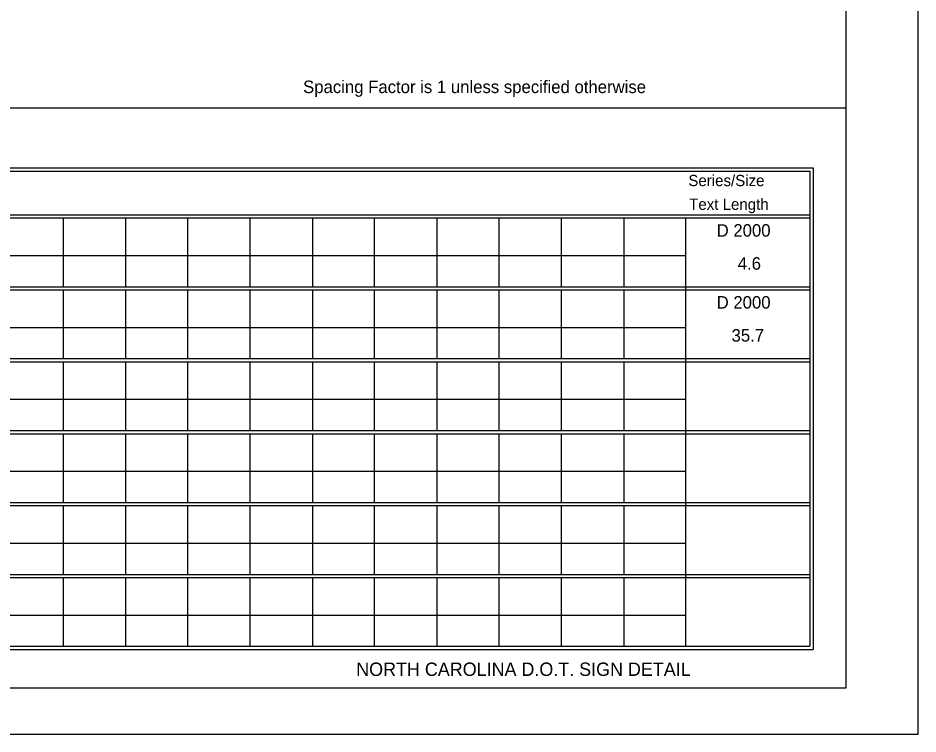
# Model space of a CAD drawing. Extents: x 1708.4 to 1771.6, y 238.3 to 283.4.
# Drawn here: x 1758.4 to 1771.62, y 262.41 to 272.92 of the extents above; entities that cross this region are included whole.
import ezdxf

# ---------------------------------------------------------------- set-up
doc = ezdxf.new("R2010")
doc.units = 0
doc.layers.add('Level 6', color=7, linetype='Continuous')
doc.layers.add('Level 9', color=7, linetype='Continuous')

msp = doc.modelspace()

# ---------------------------------------------------------------- linework, layer by layer
at = {"layer": 'Level 6'}
for p, q in [((1753.405, 271.606), (1770.56, 271.606)), ((1742.611, 270.034), (1764.378, 270.034)), ((1763.404, 270.034), (1770.033, 270.034)), ((1742.611, 269.988), (1764.378, 269.988)), ((1759.066, 269.988), (1759.066, 268.978)), ((1759.984, 269.988), (1759.984, 268.978)), ((1760.892, 269.988), (1760.892, 268.978)), ((1761.81, 269.988), (1761.81, 268.978)), ((1762.728, 269.988), (1762.728, 268.978)), ((1763.404, 269.988), (1770.033, 269.988)), ((1763.636, 269.988), (1763.636, 268.978)), ((1763.636, 269.988), (1763.636, 268.978)), ((1764.554, 269.988), (1764.554, 268.978)), ((1765.463, 269.988), (1765.463, 268.978)), ((1766.38, 269.988), (1766.38, 268.978)), ((1767.298, 269.988), (1767.298, 268.978)), ((1768.207, 269.988), (1768.207, 263.768)), ((1743.529, 269.437), (1764.378, 269.437)), ((1763.404, 269.437), (1768.207, 269.437)), ((1768.207, 269.228), (1768.207, 268.978)), ((1742.611, 268.978), (1764.378, 268.978)), ((1763.404, 268.978), (1770.033, 268.978)), ((1742.611, 268.932), (1764.378, 268.932)), ((1759.066, 268.932), (1759.066, 267.922)), ((1759.984, 268.932), (1759.984, 267.922)), ((1760.892, 268.932), (1760.892, 267.922)), ((1761.81, 268.932), (1761.81, 267.922)), ((1762.728, 268.932), (1762.728, 267.922)), ((1763.404, 268.932), (1770.033, 268.932)), ((1763.636, 268.932), (1763.636, 267.922)), ((1763.636, 268.932), (1763.636, 267.922)), ((1764.554, 268.932), (1764.554, 267.922)), ((1765.463, 268.932), (1765.463, 267.922)), ((1766.38, 268.932), (1766.38, 267.922)), ((1767.298, 268.932), (1767.298, 267.922)), ((1768.207, 268.932), (1768.207, 268.453)), ((1743.529, 268.381), (1764.378, 268.381)), ((1763.404, 268.381), (1768.207, 268.381)), ((1768.207, 268.251), (1768.207, 267.922)), ((1742.611, 267.922), (1764.378, 267.922)), ((1763.404, 267.922), (1770.033, 267.922)), ((1742.611, 267.876), (1764.378, 267.876)), ((1759.066, 267.876), (1759.066, 266.866)), ((1759.984, 267.876), (1759.984, 266.866)), ((1760.892, 267.876), (1760.892, 266.866)), ((1761.81, 267.876), (1761.81, 266.866)), ((1762.728, 267.876), (1762.728, 266.866)), ((1763.404, 267.876), (1770.033, 267.876)), ((1763.636, 267.876), (1763.636, 266.866)), ((1763.636, 267.876), (1763.636, 266.866)), ((1764.554, 267.876), (1764.554, 266.866)), ((1765.463, 267.876), (1765.463, 266.866)), ((1766.38, 267.876), (1766.38, 266.866)), ((1767.298, 267.876), (1767.298, 266.866)), ((1768.207, 267.876), (1768.207, 267.466)), ((1743.529, 267.325), (1764.378, 267.325)), ((1763.404, 267.325), (1768.207, 267.325)), ((1768.207, 267.164), (1768.207, 266.866)), ((1742.611, 266.866), (1764.378, 266.866)), ((1763.404, 266.866), (1770.033, 266.866)), ((1742.611, 266.82), (1764.378, 266.82)), ((1759.066, 266.82), (1759.066, 265.81)), ((1759.984, 266.82), (1759.984, 265.81)), ((1760.892, 266.82), (1760.892, 265.81)), ((1761.81, 266.82), (1761.81, 265.81)), ((1762.728, 266.82), (1762.728, 265.81)), ((1763.404, 266.82), (1770.033, 266.82)), ((1763.636, 266.82), (1763.636, 265.81)), ((1763.636, 266.82), (1763.636, 265.81)), ((1764.554, 266.82), (1764.554, 265.81)), ((1765.463, 266.82), (1765.463, 265.81)), ((1766.38, 266.82), (1766.38, 265.81)), ((1767.298, 266.82), (1767.298, 265.81)), ((1768.207, 266.82), (1768.207, 266.378)), ((1743.529, 266.269), (1764.378, 266.269)), ((1763.404, 266.269), (1768.207, 266.269)), ((1768.207, 266.076), (1768.207, 265.81)), ((1759.066, 265.928), (1759.066, 265.81)), ((1759.984, 265.928), (1759.984, 265.81)), ((1760.892, 265.928), (1760.892, 265.81)), ((1761.81, 265.928), (1761.81, 265.81)), ((1762.728, 265.928), (1762.728, 265.81)), ((1763.636, 265.928), (1763.636, 265.81)), ((1763.636, 265.928), (1763.636, 265.81)), ((1764.554, 265.928), (1764.554, 265.81)), ((1765.463, 265.928), (1765.463, 265.81)), ((1766.38, 265.928), (1766.38, 265.81)), ((1767.298, 265.928), (1767.298, 265.81)), ((1768.207, 265.928), (1768.207, 265.81)), ((1742.611, 265.81), (1764.378, 265.81)), ((1742.611, 265.81), (1764.378, 265.81)), ((1763.404, 265.81), (1770.033, 265.81)), ((1763.404, 265.81), (1770.033, 265.81)), ((1742.611, 265.764), (1764.378, 265.764)), ((1742.611, 265.764), (1764.378, 265.764)), ((1759.066, 265.764), (1759.066, 264.821)), ((1759.066, 265.764), (1759.066, 264.754)), ((1759.984, 265.764), (1759.984, 264.821)), ((1759.984, 265.764), (1759.984, 264.754)), ((1760.892, 265.764), (1760.892, 264.821)), ((1760.892, 265.764), (1760.892, 264.754)), ((1761.81, 265.764), (1761.81, 264.821)), ((1761.81, 265.764), (1761.81, 264.754)), ((1762.728, 265.764), (1762.728, 264.821)), ((1762.728, 265.764), (1762.728, 264.754)), ((1763.404, 265.764), (1770.033, 265.764)), ((1763.404, 265.764), (1770.033, 265.764)), ((1763.636, 265.764), (1763.636, 264.821)), ((1763.636, 265.764), (1763.636, 264.754)), ((1763.636, 265.764), (1763.636, 264.821)), ((1763.636, 265.764), (1763.636, 264.754)), ((1764.554, 265.764), (1764.554, 264.821)), ((1764.554, 265.764), (1764.554, 264.754)), ((1765.463, 265.764), (1765.463, 264.821)), ((1765.463, 265.764), (1765.463, 264.754)), ((1766.38, 265.764), (1766.38, 264.821)), ((1766.38, 265.764), (1766.38, 264.754)), ((1767.298, 265.764), (1767.298, 264.821)), ((1767.298, 265.764), (1767.298, 264.754)), ((1768.207, 265.764), (1768.207, 265.31)), ((1768.207, 265.764), (1768.207, 265.31)), ((1743.529, 265.214), (1764.378, 265.214)), ((1743.529, 265.214), (1764.378, 265.214)), ((1763.404, 265.214), (1768.207, 265.214)), ((1763.404, 265.214), (1767.969, 265.214)), ((1768.207, 265.048), (1768.207, 264.821)), ((1768.207, 265.048), (1768.207, 264.754)), ((1759.066, 264.872), (1759.066, 264.754)), ((1759.984, 264.872), (1759.984, 264.754)), ((1760.892, 264.872), (1760.892, 264.754)), ((1761.81, 264.872), (1761.81, 264.754)), ((1762.728, 264.872), (1762.728, 264.754)), ((1763.636, 264.872), (1763.636, 264.754)), ((1763.636, 264.872), (1763.636, 264.754)), ((1764.554, 264.872), (1764.554, 264.754)), ((1765.463, 264.872), (1765.463, 264.754)), ((1766.38, 264.872), (1766.38, 264.754)), ((1767.298, 264.872), (1767.298, 264.754)), ((1768.207, 264.872), (1768.207, 264.754)), ((1742.611, 264.754), (1764.378, 264.754)), ((1742.611, 264.754), (1764.378, 264.754)), ((1763.404, 264.754), (1770.033, 264.754)), ((1763.404, 264.754), (1770.033, 264.754)), ((1742.611, 264.709), (1764.378, 264.709)), ((1742.611, 264.709), (1764.378, 264.709)), ((1759.066, 264.709), (1759.066, 263.699)), ((1759.066, 264.709), (1759.066, 263.699)), ((1759.984, 264.709), (1759.984, 263.699)), ((1759.984, 264.709), (1759.984, 263.699)), ((1760.892, 264.709), (1760.892, 263.699)), ((1760.892, 264.709), (1760.892, 263.699)), ((1761.81, 264.709), (1761.81, 263.699)), ((1761.81, 264.709), (1761.81, 263.699)), ((1762.728, 264.709), (1762.728, 263.699)), ((1762.728, 264.709), (1762.728, 263.699)), ((1763.404, 264.709), (1770.033, 264.709)), ((1763.404, 264.709), (1770.033, 264.709)), ((1763.636, 264.709), (1763.636, 263.699)), ((1763.636, 264.709), (1763.636, 263.699)), ((1763.636, 264.709), (1763.636, 263.699)), ((1763.636, 264.709), (1763.636, 263.699)), ((1764.554, 264.709), (1764.554, 263.699)), ((1764.554, 264.709), (1764.554, 263.699)), ((1765.463, 264.709), (1765.463, 263.699)), ((1765.463, 264.709), (1765.463, 263.699)), ((1766.38, 264.709), (1766.38, 263.699)), ((1766.38, 264.709), (1766.38, 263.699)), ((1767.298, 264.709), (1767.298, 263.699)), ((1767.298, 264.709), (1767.298, 263.699)), ((1768.207, 264.709), (1768.207, 264.283)), ((1768.207, 264.709), (1768.207, 264.283)), ((1743.529, 264.158), (1764.378, 264.158)), ((1743.529, 264.158), (1764.378, 264.158)), ((1763.404, 264.158), (1768.207, 264.158)), ((1763.404, 264.158), (1768.031, 264.158)), ((1768.207, 263.961), (1768.207, 263.699)), ((1768.207, 263.961), (1768.207, 263.699)), ((1742.611, 263.699), (1764.378, 263.699)), ((1742.611, 263.699), (1764.378, 263.699)), ((1763.404, 263.699), (1770.033, 263.699)), ((1763.404, 263.699), (1770.033, 263.699)), ((1742.564, 263.653), (1764.378, 263.653)), ((1742.611, 263.653), (1764.378, 263.653)), ((1763.404, 263.653), (1770.08, 263.653)), ((1763.404, 263.653), (1770.033, 263.653))]:
    msp.add_line(p, q, dxfattribs=at)
msp.add_lwpolyline([(1742.248, 282.741), (1770.56, 282.741), (1770.56, 263.084), (1742.248, 263.084)], close=True, dxfattribs=at)
for points in [[(1742.564, 264.821), (1742.564, 270.723), (1764.378, 270.723)], [(1742.611, 264.821), (1742.611, 270.677), (1764.378, 270.677)], [(1763.404, 270.723), (1770.08, 270.723), (1770.08, 264.821)], [(1763.404, 270.677), (1770.033, 270.677), (1770.033, 264.821)], [(1770.033, 265.928), (1770.033, 263.699)], [(1770.08, 265.928), (1770.08, 263.653)]]:
    msp.add_lwpolyline(points, dxfattribs=at)
at = {"layer": 'Level 9'}
msp.add_lwpolyline([(1741.558, 262.411), (1771.62, 262.411), (1771.62, 283.435), (1741.558, 283.435)], close=True, dxfattribs=at)

# ---------------------------------------------------------------- texts
at = {"layer": 'Level 6'}
for s, height, p in [('Spacing Factor is 1 unless specified otherwise', 0.18363, (1762.59, 271.821)), ('Series/Size', 0.16527, (1768.248, 270.455)), ('Text Length', 0.16527, (1768.26, 270.107)), ('NORTH CAROLINA D.O.T. SIGN DETAIL', 0.19675, (1763.37, 263.264))]:
    msp.add_text(s, height=height, rotation=360, dxfattribs=at).set_placement(p)
for s, p in [('D 2000', (1768.663, 269.713)), ('4.6', (1768.973, 269.228)), ('D 2000', (1768.663, 268.657)), ('35.7', (1768.882, 268.172))]:
    msp.add_text(s, height=0.1836, dxfattribs=at).set_placement(p)

doc.saveas('drawing.dxf')
